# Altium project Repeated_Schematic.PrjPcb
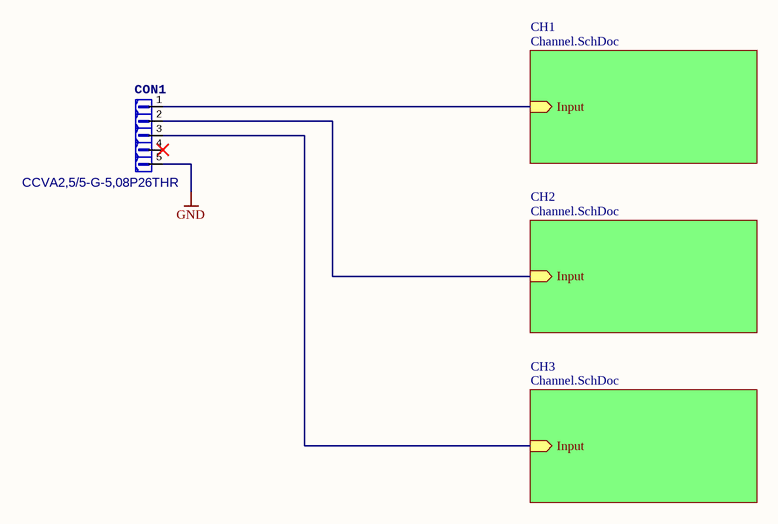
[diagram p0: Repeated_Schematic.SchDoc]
2 sheets, 7 parts. Net scope: hierarchical (ports join the sheet entries above them; power ports are global).
Sheets:
  Repeated_Schematic.SchDoc
    CH1 = Channel.SchDoc
    CH2 = Channel.SchDoc
    CH3 = Channel.SchDoc

## Sheet Repeated_Schematic.SchDoc
size A4; SheetNumber: 1; SheetTotal: 2

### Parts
CON1  CCVA2,5/5-G-5,08P26THR  [CCVA2,5/5-G-5,08P26THR]

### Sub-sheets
CH1 = Channel.SchDoc: Input (in)
CH2 = Channel.SchDoc: Input (in)
CH3 = Channel.SchDoc: Input (in)

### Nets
GND: CON1.5
NetCON1_1: CON1.1 ; sheet CH1/Input
NetCON1_2: CON1.2 ; sheet CH2/Input
NetCON1_3: CON1.3 ; sheet CH3/Input

Not connected (* = marked no-connect by the designer): CON1 4*

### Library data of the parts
CON1 = CCVA2,5/5-G-5,08P26THR: CCVA2,5/5-G-5,08P26THR 7polig 5.08mm Raster; BE-NR: BE-30-00271

## Sheet Channel.SchDoc
size A4; SheetNumber: 2; SheetTotal: 2
Used 3 times, as channels CH1, CH2, CH3. Parts and nets are listed once, with the designators drawn on the sheet.
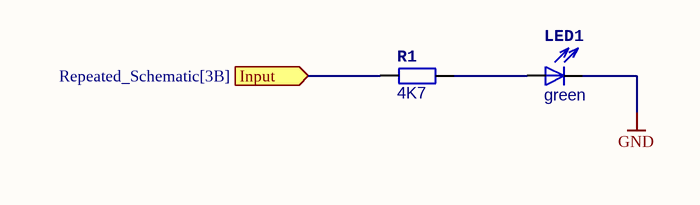
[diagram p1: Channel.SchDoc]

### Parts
LED1  green  [LED0603]
R1  4K7  [R0603]

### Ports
Input (in, see Repeated_Schematic[3B])

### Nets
GND: LED1.C
Input: R1.1 ; port Input
NetLED1_A: LED1.A R1.2

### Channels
CH1: designators end in _CH1; ports Input=NetCON1_1
CH2: designators end in _CH2; ports Input=NetCON1_2
CH3: designators end in _CH3; ports Input=NetCON1_3

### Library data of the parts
LED1 = LED_0603_GREEN: GREEN LED, 0603, 430mcd, 140°, VF 3.2V, VR 5V; BE-NR: BH-90-00064; TMP: -40°C to +85°C; IF: 30mA; ORDER-NO: 150060GS75000; MNF: WE
R1 = 4K7-0603: 4k7,  1%, TK100, 0.1W; BE-NR: BP-11-00141

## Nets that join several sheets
GND: Repeated_Schematic (CON1.5), CH1 (LED1_CH1.C), CH2 (LED1_CH2.C), CH3 (LED1_CH3.C)
NetCON1_1: Repeated_Schematic (CON1.1), CH1 (R1_CH1.1)
NetCON1_2: Repeated_Schematic (CON1.2), CH2 (R1_CH2.1)
NetCON1_3: Repeated_Schematic (CON1.3), CH3 (R1_CH3.1)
